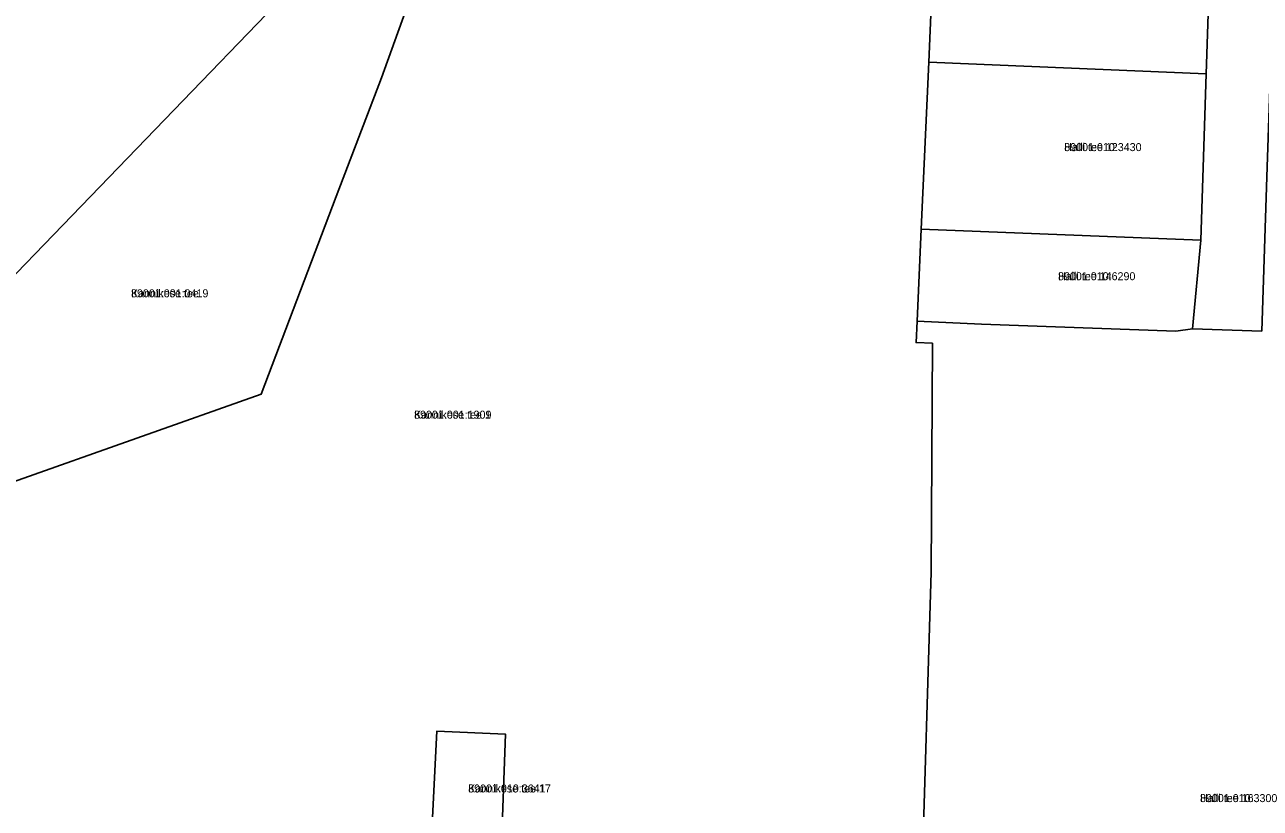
# Model space of a CAD drawing. Extents: x 526849 to 562296, y 6591741 to 6618546.
# Drawn here: x 547707.4 to 547939, y 6596107.7 to 6596254.7 of the extents above; entities that cross this region are included whole.
import ezdxf

# ---------------------------------------------------------------- set-up
doc = ezdxf.new("R2010")
doc.units = 0
for name, color, linetype in [('L_AADRESS', 7, 'Continuous'), ('PIIR', 7, 'Continuous'), ('TUNNUS', 7, 'Continuous')]:
    doc.layers.add(name, color=color, linetype=linetype)

msp = doc.modelspace()

# ---------------------------------------------------------------- linework, layer by layer
at = {"layer": 'PIIR'}
for points in [[(547932.7, 6596359.06), (547933.66, 6596399.62), (547945.49, 6596393.62), (547944.42, 6596351.23), (547943.56, 6596324.88), (547942.96, 6596307.14), (547942.07, 6596280.58), (547941.8, 6596272.12), (547940.26, 6596226.11), (547939.3, 6596197.22), (547926.35, 6596197.63), (547927.86, 6596214.28), (547928.9, 6596245.47), (547929.71, 6596269.8), (547930.45, 6596291.8), (547931.17, 6596313.53)], [(547877.89, 6596271.47), (547929.71, 6596269.8), (547928.9, 6596245.47), (547876.9, 6596247.63)], [(547928.9, 6596245.47), (547927.86, 6596214.28), (547875.48, 6596216.32), (547876.9, 6596247.63)], [(547927.86, 6596214.28), (547926.35, 6596197.63), (547923.23, 6596197.18), (547886.79, 6596198.52), (547874.71, 6596199.06), (547875.48, 6596216.32)], [(547783.54, 6596099.75), (547784.63, 6596122.17), (547797.54, 6596121.61), (547796.69, 6596099.28)]]:
    msp.add_lwpolyline(points, close=True, dxfattribs=at)
for points in [[(547690.17, 6596191.87), (547763.12, 6596267.42), (547767.08, 6596279.49), (547771, 6596278.42), (547774.08, 6596289.49), (547777.18, 6596300.42), (547780.32, 6596311.52), (547783.37, 6596322.33), (547786.43, 6596333.19), (547789.46, 6596343.91), (547792.53, 6596354.72), (547795.65, 6596365.69), (547818.08, 6596359.67), (547816.28, 6596354.76), (547786.25, 6596291.35), (547784.51, 6596273.18), (547774.28, 6596244.68), (547765.81, 6596222.42), (547751.73, 6596185.38), (547705.14, 6596168.88)], [(547706.39, 6596096.06), (547678.12, 6596135.41), (547705.14, 6596168.88), (547751.73, 6596185.38), (547765.81, 6596222.42), (547774.28, 6596244.68), (547784.51, 6596273.18), (547786.25, 6596291.35), (547816.28, 6596354.76), (547818.08, 6596359.67), (547851.56, 6596357.26), (547867.85, 6596356.78), (547882.68, 6596357.65), (547882.59, 6596354.87), (547879.67, 6596315.25), (547878.79, 6596293.54), (547877.89, 6596271.47), (547876.9, 6596247.63), (547875.48, 6596216.32), (547874.71, 6596199.06), (547874.51, 6596195.05), (547877.57, 6596194.93), (547877.34, 6596152.04), (547875.55, 6596092.04)], [(547763.12, 6596267.42), (547690.17, 6596191.87)], [(547961.48, 6596017.57), (547929.15, 6596018.83), (547922.64, 6596025.2), (547889.3, 6596026.45), (547881.71, 6596026.74), (547884.07, 6596091.64), (547875.55, 6596092.04), (547877.34, 6596152.04), (547877.57, 6596194.93), (547874.51, 6596195.05), (547874.71, 6596199.06), (547886.79, 6596198.52), (547923.23, 6596197.18), (547926.35, 6596197.63), (547939.3, 6596197.22)], [(547796.69, 6596099.28), (547797.54, 6596121.61), (547784.63, 6596122.17), (547783.54, 6596099.75)]]:
    msp.add_lwpolyline(points, dxfattribs=at)

# ---------------------------------------------------------------- texts
at = {"layer": 'L_AADRESS'}
for s, p in [('Halli tee 12', (547902.28, 6596230.96)), ('Halli tee 14', (547901.12, 6596206.75)), ('Kannikese tee', (547727.33, 6596203.55)), ('Kannikese tee 1', (547780.4, 6596180.79)), ('Kannikese tee 17', (547790.54, 6596110.71)), ('Halli tee 16', (547927.73, 6596108.9))]:
    msp.add_text(s, height=1.5, dxfattribs=at).set_placement(p)
at = {"layer": 'TUNNUS'}
for s, p in [('89001:010:3430', (547902.28, 6596230.96)), ('89001:010:6290', (547901.12, 6596206.75)), ('89001:001:0419', (547727.33, 6596203.55)), ('89001:001:1909', (547780.4, 6596180.79)), ('89001:010:3641', (547790.54, 6596110.71)), ('89001:010:3300', (547927.73, 6596108.9))]:
    msp.add_text(s, height=1.5, dxfattribs=at).set_placement(p)

doc.saveas('drawing.dxf')
